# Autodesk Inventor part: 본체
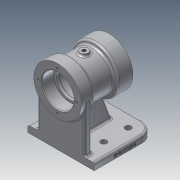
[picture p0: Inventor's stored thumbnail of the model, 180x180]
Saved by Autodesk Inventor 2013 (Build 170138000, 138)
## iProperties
Created: 2020-06
Part Number: 본체
Material: 알루미늄 6061
Document SubType Name: Modeling
Designer: 19
Density: 1 g/cm^3
Author: 19
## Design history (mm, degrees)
sketch "스케치17"
  geometry: C1 r 35 at (0, 0); 1 further point
  constraints: 1 centre point, 1 coincident
  dimensions: "d76" = 70 diameter of C1
extrude "돌출12" new body sketch "스케치17" distance "d77" = 22; taper "d78" = 0 deg
sketch "스케치18"
  geometry: C1 r 35 at (0, 0) reference; C2 r 29 at (0, 0)
  constraints: 1 centre point, 1 coincident
  dimensions: "d79" = 58 diameter of C2
extrude "돌출13" join sketch "스케치18" distance "d80" = 34; taper "d81" = 0 deg
sketch "스케치19"
  geometry: C1 r 29 at (0, 0) reference; C2 r 35 at (0, 0)
  constraints: 1 centre point, 1 coincident
  dimensions: "d82" = 70 diameter of C2
extrude "돌출14" join sketch "스케치19" distance "d83" = 20; taper "d84" = 0 deg
sketch "스케치20"
  geometry: C1 r 35 at (0, 0) reference; C2 r 23.5 at (0, 0)
  constraints: 1 centre point, 1 coincident
  dimensions: "d85" = 47 diameter of C2
extrude "돌출15" cut sketch "스케치20" distance "d86" = 18; taper "d87" = 0 deg
sketch "스케치21"
  geometry: C1 r 23.5 at (0, 0) reference; C2 r 20 at (0, 0)
  constraints: 1 centre point, 1 coincident
  dimensions: "d88" = 40 diameter of C2
extrude "돌출16" cut sketch "스케치21" distance "d89" = 6; taper "d90" = 0 deg
sketch "스케치22"
  geometry: C1 r 20 at (0, 0) reference; C2 r 23 at (0, 0)
  constraints: 1 centre point, 1 coincident
  dimensions: "d91" = 46 diameter of C2
extrude "돌출17" cut sketch "스케치22" distance "d92" = 30; taper "d93" = 0 deg
sketch "스케치23"
  geometry: C1 r 35 at (0, 0) reference; C2 r 23.5 at (0, 0)
  constraints: 1 centre point, 1 coincident
  dimensions: "d94" = 47 diameter of C2
extrude "돌출18" cut sketch "스케치23" distance "d95" = 18; taper "d96" = 0 deg
sketch "스케치24"
  geometry: C1 r 23.5 at (0, 0) reference; C2 r 20 at (0, 0)
  constraints: 1 centre point, 1 coincident
  dimensions: "d97" = 40 diameter of C2
extrude "돌출19" cut sketch "스케치24" distance "d98" = 6; taper "d99" = 0 deg
node "작업 평면4"
sketch "스케치25"
  geometry: L1 (-35, -76)-(35, -76) reference; L2 (-49, -71)-(49, -71); L3 (-49, -71)-(-49, 19); L4 (-49, 19)-(49, 19); L5 (49, 19)-(49, -71); 3 further points
  constraints: 8 end point, 3 perpendicular, 2 midpoint, 1 parallel, 1 vertical alignment
  dimensions: "d101" = 98 distance of L2.start L2.end; "d102" = 5 distance of point (0, -76) point (0, -71); "d103" = 90 distance of L2.start L3.end
extrude "돌출20" join sketch "스케치25" distance "d104" = 10; taper "d105" = 0 deg
sketch "스케치26"
  geometry: L1 (-71, 49)-(-71, -49) reference; L2 (-71, 35)-(-61, 35); L3 (-61, 35)-(-61, -35); L4 (-61, -35)-(-71, -35); L5 (-71, -35)-(-71, 35); 2 further points
  constraints: 8 end point, 2 midpoint, 2 parallel, 1 horizontal, 1 perpendicular
  dimensions: "d106" = 10 distance of L3.end L4.end; "d107" = 70 distance of L2.end L3.end
extrude "돌출21" join sketch "스케치26" stored distance "d108" = 10; taper "d109" = 0 deg
sketch "스케치27"
  geometry: L1 (-61, 35)-(-61, -35) reference; L2 (-61, 5)-(-1, 5); L3 (-1, 5)-(-1, -5); L4 (-1, -5)-(-61, -5); L5 (-61, -5)-(-61, 5); 2 further points
  constraints: 8 end point, 2 midpoint, 2 parallel, 1 horizontal, 1 perpendicular
  dimensions: "d110" = 60 distance of L3.end L4.end; "d111" = 10 distance of L2.end L3.end
extrude "돌출22" join sketch "스케치27" stored distance "d112" = 10; taper "d113" = 0 deg
feature "면 기울기2" dims angle "d114" = 20 deg
fillet "모깎기3" dims "d115" = 20
sketch "스케치28"
  geometry: A1 r 20 centre (-1, -29) between (-1, -49) and (19, -29) reference; A2 r 20 centre (-1, 29) between (19, 29) and (-1, 49) reference; 5 further points
  constraints: 2 coincident, 2 horizontal alignment, 1 vertical alignment
  dimensions: "d116" = 36 distance of point (-1, 29) point (-37, 29)
hole "구멍4" sketch "스케치28" at (-1, 29), (-1, -29), (-37, -29), (-37, 29) diameter "d118" = 9; stored, may be unused: countersink angle "d122" = 90 deg, drill point angle "d124" = 118 deg; dims "d119" = 10, "d120" = 4, "d121" = 2, "d123" = 12
sketch "스케치29" dims "d125" = 57
  geometry: C1 r 23.5 at (0, 0) reference; C2 r 35 at (0, 0) reference; 2 further points
  constraints: 2 vertical alignment, 1 coincident, 2 other
hole "구멍5" sketch "스케치29" at (0, 28.5) diameter "d126" = 3.242; stored, may be unused: countersink angle "d130" = 90 deg, drill point angle "d132" = 118 deg; dims "d127" = 10, "d128" = 4, "d129" = 2, "d131" = 12
sketch "스케치30" dims "d136" = 57
  geometry: C1 r 23.5 at (0, 0) reference; C2 r 35 at (0, 0) reference; 2 further points
  constraints: 2 vertical alignment, 1 coincident, 2 other
hole "구멍6" sketch "스케치30" at (0, 28.5) diameter "d137" = 3.242; stored, may be unused: countersink angle "d141" = 90 deg, drill point angle "d143" = 118 deg; dims "d138" = 10, "d139" = 4, "d140" = 2, "d142" = 12
node "작업 평면5"
sketch "스케치31"
  geometry: L1 (-35, -76)-(35, -76) reference; C1 r 6 at (0, -37); 2 further points
  constraints: 1 centre point, 1 midpoint, 1 vertical alignment
  dimensions: "d148" = 12 diameter of C1; "d149" = 39 distance of point (0, -76) C1.centre
extrude "돌출23" join sketch "스케치31" stored distance "d150" = 10; taper "d151" = 0 deg
sketch "스케치32"
  geometry: C1 r 6 at (0, 0) reference; 2 further points
  constraints: 1 coincident
hole "구멍7" sketch "스케치32" at (0, 0) diameter "d152" = 5.188; stored, may be unused: countersink angle "d156" = 90 deg, drill point angle "d158" = 0 deg; dims "d153" = 20, "d154" = 4, "d155" = 2, "d157" = 20
fillet "모깎기4" dims "d159" = 0.3
fillet "모깎기5" dims "d160" = 3
chamfer "모따기1" distance "d161" = 1; stored, may be unused: second distance "d162" = 2, angle "d163" = 45 deg
fillet "모깎기6" dims "d164" = 3
fillet "모깎기7" dims "d165" = 3
fillet "모깎기8" dims "d166" = 3
fillet "모깎기9" dims "d167" = 3
fillet "모깎기10" dims "d168" = 3
fillet "모깎기11" dims "d169" = 3
fillet "모깎기12" dims "d170" = 3
fillet "모깎기13" dims "d171" = 3
fillet "모깎기14" dims "d172" = 3
fillet "모깎기15" dims "d173" = 3
fillet "모깎기16" dims "d174" = 3
fillet "모깎기17" dims "d175" = 3
fillet "모깎기18" dims "d176" = 3
fillet "모깎기19" dims "d177" = 3
sketch "스케치33"
  geometry: L1 (0, 0)-(-7, 0) reference; L2 (0, 0)-(0, 70) reference; 2 further points
  constraints: 1 other
  dimensions: "d178" = 45 distance from line of L1 point (-4, 45); "d179" = 4 distance from line of L2 point (-4, 45)
feature "엠보싱1" sketch "스케치33" dims "d180" = 0.5, "d181" = 0
node "솔리드2"
pattern_circular "원형 패턴2" dims angle "d134" = 360 deg
pattern_circular "원형 패턴3" dims angle "d145" = 360 deg
other parameters: "d147" = -32
